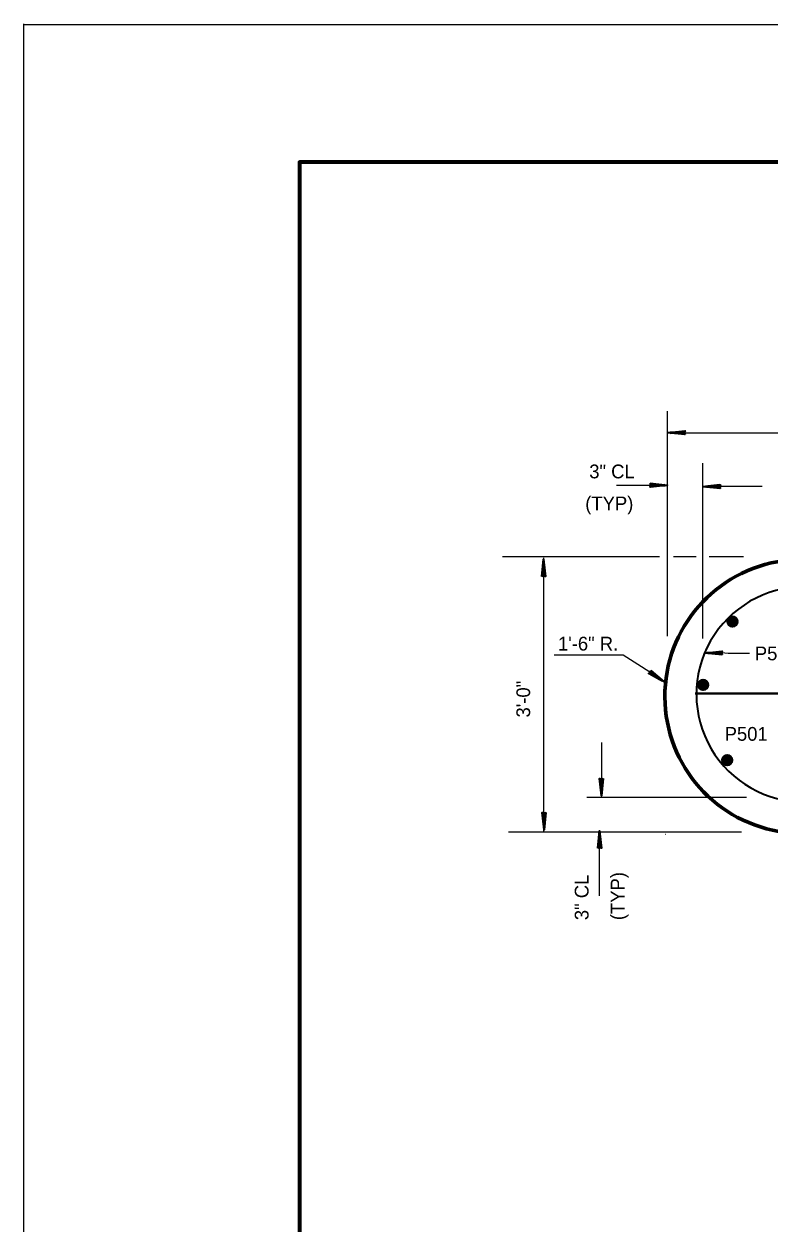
# Model space of a CAD drawing. Extents: x 3.64 to 6.84, y -0.8 to 1.19.
# Drawn here: x 3.645 to 4.095, y 0.467 to 1.192 of the extents above; entities that cross this region are included whole.
import ezdxf

# ---------------------------------------------------------------- set-up
doc = ezdxf.new("R2010")
doc.units = 0
doc.header["$LTSCALE"] = 0.0033
doc.layers.add('1', color=7, linetype='Continuous', lineweight=40)

msp = doc.modelspace()

# ---------------------------------------------------------------- linework, layer by layer
at = {"layer": '1', "lineweight": 13}
for p, q in [((3.644833, -0.795833), (3.644833, 1.192417)), ((3.644833, 1.192083), (6.84125, 1.192083)), ((4.034167, 0.822083), (4.034167, 0.958167)), ((4.034083, 0.945083), (4.494, 0.945083)), ((4.0555, 0.82075), (4.0555, 0.926667)), ((4.003333, 0.9135), (4.024167, 0.9135)), ((4.056167, 0.912833), (4.09125, 0.912833)), ((3.934333, 0.87025), (4.029167, 0.87025)), ((3.959167, 0.8695), (3.959167, 0.7035)), ((4.034167, 0.86875), (4.034167, 0.868833)), ((4.037667, 0.87025), (4.051333, 0.87025)), ((4.059333, 0.87025), (4.080083, 0.87025)), ((3.99425, 0.75775), (3.99425, 0.726333)), ((3.98525, 0.724667), (4.081917, 0.724667)), ((3.937917, 0.70375), (4.07875, 0.70375)), ((3.993, 0.665083), (3.993, 0.702583)), ((4.033167, 0.702083), (4.032833, 0.702083))]:
    msp.add_line(p, q, dxfattribs=at)
at = {"layer": '1', "lineweight": 35}
for p, q in [((4.04475, 0.945083), (4.034167, 0.945083)), ((4.0445, 0.94425), (4.036667, 0.94525)), ((4.0445, 0.94425), (4.036667, 0.945083)), ((4.0445, 0.944083), (4.036667, 0.945)), ((4.0445, 0.944083), (4.036667, 0.945)), ((4.0445, 0.944167), (4.036667, 0.945)), ((4.0445, 0.946167), (4.037167, 0.945333)), ((4.0445, 0.946), (4.037167, 0.94525)), ((4.0445, 0.945917), (4.037167, 0.945083)), ((4.044583, 0.94575), (4.03725, 0.945)), ((4.02375, 0.9145), (4.031583, 0.913583)), ((4.02375, 0.9145), (4.031583, 0.913583)), ((4.02375, 0.914417), (4.031583, 0.913583)), ((4.02375, 0.914333), (4.031583, 0.9135)), ((4.02375, 0.914333), (4.031583, 0.913333)), ((4.0235, 0.9135), (4.034083, 0.9135)), ((4.023667, 0.912833), (4.031, 0.913583)), ((4.02375, 0.912667), (4.031083, 0.9135)), ((4.02375, 0.912583), (4.031083, 0.913333)), ((4.02375, 0.912417), (4.031083, 0.91325)), ((4.066083, 0.9125), (4.0555, 0.9125)), ((4.065833, 0.911667), (4.058, 0.912667)), ((4.065833, 0.911667), (4.058, 0.9125)), ((4.065833, 0.9115), (4.058, 0.912417)), ((4.065833, 0.9115), (4.058, 0.912417)), ((4.065833, 0.911583), (4.058, 0.912417)), ((4.065833, 0.913583), (4.0585, 0.91275)), ((4.065833, 0.913417), (4.0585, 0.912667)), ((4.065833, 0.913333), (4.0585, 0.9125)), ((4.065917, 0.913167), (4.058583, 0.912417)), ((3.958167, 0.858417), (3.959083, 0.86625)), ((3.958167, 0.858417), (3.959083, 0.86625)), ((3.95825, 0.858417), (3.959083, 0.86625)), ((3.958333, 0.858417), (3.959167, 0.86625)), ((3.958333, 0.858417), (3.959333, 0.86625)), ((3.959833, 0.858333), (3.959083, 0.865667)), ((3.959167, 0.858167), (3.959167, 0.86875)), ((3.96, 0.858417), (3.959167, 0.86575)), ((3.960083, 0.858417), (3.959333, 0.86575)), ((3.96025, 0.858417), (3.959417, 0.86575)), ((4.067, 0.812917), (4.059667, 0.812083)), ((4.067, 0.81275), (4.059667, 0.812)), ((4.067, 0.812667), (4.059667, 0.811833)), ((4.067083, 0.8125), (4.05975, 0.81175)), ((4.06725, 0.811833), (4.056667, 0.811833)), ((4.067, 0.811), (4.059167, 0.812)), ((4.067, 0.811), (4.059167, 0.811833)), ((4.067, 0.810833), (4.059167, 0.81175)), ((4.067, 0.810833), (4.059167, 0.81175)), ((4.067, 0.810917), (4.059167, 0.81175)), ((4.022917, 0.7995), (4.029417, 0.796)), ((4.023, 0.799667), (4.029583, 0.796167)), ((4.023083, 0.799917), (4.029583, 0.79625)), ((4.023083, 0.799583), (4.0295, 0.796)), ((4.023333, 0.800583), (4.032, 0.7945)), ((4.024, 0.801083), (4.03, 0.795917)), ((4.024, 0.801083), (4.029833, 0.79575)), ((4.024083, 0.801167), (4.030083, 0.796)), ((4.024167, 0.801167), (4.030083, 0.796)), ((4.024167, 0.801167), (4.030083, 0.796)), ((3.993083, 0.735833), (3.993917, 0.7285)), ((3.99325, 0.735833), (3.994, 0.7285)), ((3.993333, 0.735833), (3.994167, 0.7285)), ((3.9935, 0.735917), (3.99425, 0.728583)), ((3.995, 0.735833), (3.994, 0.728)), ((3.994167, 0.736083), (3.994167, 0.7255)), ((3.995, 0.735833), (3.994167, 0.728)), ((3.995167, 0.735833), (3.99425, 0.728)), ((3.995167, 0.735833), (3.99425, 0.728)), ((3.995083, 0.735833), (3.99425, 0.728)), ((3.958333, 0.71525), (3.959167, 0.707917)), ((3.9585, 0.71525), (3.95925, 0.707917)), ((3.958583, 0.71525), (3.959417, 0.707917)), ((3.95875, 0.715333), (3.9595, 0.708)), ((3.96025, 0.71525), (3.95925, 0.707417)), ((3.959417, 0.7155), (3.959417, 0.704917)), ((3.96025, 0.71525), (3.959417, 0.707417)), ((3.960417, 0.71525), (3.9595, 0.707417)), ((3.960417, 0.71525), (3.9595, 0.707417)), ((3.960333, 0.71525), (3.9595, 0.707417)), ((3.993, 0.693833), (3.993, 0.704417)), ((3.992, 0.694083), (3.992917, 0.701917)), ((3.992, 0.694083), (3.992917, 0.701917)), ((3.992083, 0.694083), (3.992917, 0.701917)), ((3.992167, 0.694083), (3.993, 0.701917)), ((3.992167, 0.694083), (3.993167, 0.701917)), ((3.993667, 0.694), (3.992917, 0.701333)), ((3.993833, 0.694083), (3.993, 0.701417)), ((3.993917, 0.694083), (3.993167, 0.701417)), ((3.994083, 0.694083), (3.99325, 0.701417))]:
    msp.add_line(p, q, dxfattribs=at)
at = {"layer": '1', "lineweight": 60}
for p, q in [((4.075917, 0.830333), (4.071167, 0.829583)), ((4.071583, 0.8325), (4.071417, 0.829583)), ((4.071833, 0.8325), (4.071583, 0.829583)), ((4.072, 0.8325), (4.071833, 0.8295)), ((4.072167, 0.8325), (4.071917, 0.8295)), ((4.072333, 0.8325), (4.072167, 0.8295)), ((4.072583, 0.8325), (4.072417, 0.8295)), ((4.072833, 0.8325), (4.072583, 0.8295)), ((4.072917, 0.832417), (4.07275, 0.8295)), ((4.073083, 0.832417), (4.072917, 0.8295)), ((4.07325, 0.832417), (4.073083, 0.8295)), ((4.0735, 0.832417), (4.07325, 0.8295)), ((4.073667, 0.832417), (4.0735, 0.8295)), ((4.073917, 0.832333), (4.073667, 0.829417)), ((4.074167, 0.832333), (4.073917, 0.829417)), ((4.074333, 0.832333), (4.074167, 0.829417)), ((4.074417, 0.832333), (4.07425, 0.829417)), ((4.074583, 0.832333), (4.074417, 0.829417)), ((4.074667, 0.832333), (4.0745, 0.829417)), ((4.074917, 0.83225), (4.074667, 0.829333)), ((4.075083, 0.83225), (4.074917, 0.829333)), ((4.07525, 0.83225), (4.075, 0.829333)), ((4.075417, 0.83225), (4.07525, 0.829333)), ((4.075667, 0.83225), (4.0755, 0.829333)), ((4.075917, 0.830333), (4.07575, 0.832167)), ((4.058167, 0.792), (4.053417, 0.79125)), ((4.053833, 0.794167), (4.053667, 0.79125)), ((4.054083, 0.794167), (4.053833, 0.79125)), ((4.05425, 0.794167), (4.054083, 0.791167)), ((4.054417, 0.794167), (4.054167, 0.791167)), ((4.054583, 0.794167), (4.054417, 0.791167)), ((4.054833, 0.794167), (4.054667, 0.791167)), ((4.055083, 0.794167), (4.054833, 0.791167)), ((4.055167, 0.794083), (4.055, 0.791167)), ((4.055333, 0.794083), (4.055167, 0.791167)), ((4.0555, 0.794083), (4.055333, 0.791167)), ((4.05575, 0.794083), (4.0555, 0.791167)), ((4.055917, 0.794083), (4.05575, 0.791167)), ((4.056167, 0.794), (4.055917, 0.791083)), ((4.056417, 0.794), (4.056167, 0.791083)), ((4.056583, 0.794), (4.056417, 0.791083)), ((4.056667, 0.794), (4.0565, 0.791083)), ((4.056833, 0.794), (4.056667, 0.791083)), ((4.056917, 0.794), (4.05675, 0.791083)), ((4.057167, 0.793917), (4.056917, 0.791)), ((4.057333, 0.793917), (4.057167, 0.791)), ((4.0575, 0.793917), (4.05725, 0.791)), ((4.057667, 0.793917), (4.0575, 0.791)), ((4.057917, 0.793917), (4.05775, 0.791)), ((4.058167, 0.792), (4.058, 0.793833)), ((4.068417, 0.748667), (4.06825, 0.74575)), ((4.068667, 0.748667), (4.068417, 0.74575)), ((4.068833, 0.748667), (4.068667, 0.745667)), ((4.069, 0.748667), (4.06875, 0.745667)), ((4.069167, 0.748667), (4.069, 0.745667)), ((4.069417, 0.748667), (4.06925, 0.745667)), ((4.069667, 0.748667), (4.069417, 0.745667)), ((4.06975, 0.748583), (4.069583, 0.745667)), ((4.069917, 0.748583), (4.06975, 0.745667)), ((4.070083, 0.748583), (4.069917, 0.745667)), ((4.070333, 0.748583), (4.070083, 0.745667)), ((4.0705, 0.748583), (4.070333, 0.745667)), ((4.07075, 0.7485), (4.0705, 0.745583)), ((4.071, 0.7485), (4.07075, 0.745583)), ((4.071167, 0.7485), (4.071, 0.745583)), ((4.07125, 0.7485), (4.071083, 0.745583)), ((4.071417, 0.7485), (4.07125, 0.745583)), ((4.0715, 0.7485), (4.071333, 0.745583)), ((4.07175, 0.748417), (4.0715, 0.7455)), ((4.071917, 0.748417), (4.07175, 0.7455)), ((4.072083, 0.748417), (4.071833, 0.7455)), ((4.07225, 0.748417), (4.072083, 0.7455)), ((4.0725, 0.748417), (4.072333, 0.7455)), ((4.07275, 0.7465), (4.072583, 0.748333)), ((4.07275, 0.7465), (4.068, 0.74575))]:
    msp.add_line(p, q, dxfattribs=at)
at = {"layer": '1'}
for p, q in [((4.071167, 0.82975), (4.075, 0.829)), ((4.071167, 0.829583), (4.075, 0.828833)), ((4.07125, 0.83025), (4.075167, 0.8295)), ((4.07125, 0.830083), (4.075083, 0.829333)), ((4.07125, 0.829833), (4.075083, 0.829167)), ((4.071333, 0.8325), (4.075917, 0.830333)), ((4.071333, 0.830667), (4.07525, 0.829917)), ((4.071417, 0.831083), (4.07525, 0.830333)), ((4.071417, 0.830917), (4.07525, 0.830167)), ((4.0715, 0.8315), (4.075333, 0.830833)), ((4.0715, 0.831333), (4.075333, 0.830583)), ((4.071583, 0.832083), (4.0755, 0.831333)), ((4.071583, 0.831917), (4.0755, 0.831167)), ((4.071583, 0.831667), (4.075417, 0.830917)), ((4.071667, 0.8325), (4.075583, 0.831833)), ((4.071667, 0.832333), (4.075583, 0.831583)), ((4.07175, 0.832833), (4.075583, 0.832167)), ((4.0755, 0.829333), (4.07175, 0.828917)), ((4.073667, 0.832), (4.075, 0.833)), ((4.07575, 0.832167), (4.0745, 0.833333)), ((4.053417, 0.791417), (4.05725, 0.790667)), ((4.053417, 0.79125), (4.05725, 0.7905)), ((4.0535, 0.791917), (4.057417, 0.791167)), ((4.0535, 0.79175), (4.057333, 0.791)), ((4.0535, 0.7915), (4.057333, 0.790833)), ((4.053583, 0.794167), (4.058167, 0.792)), ((4.053583, 0.792333), (4.0575, 0.791583)), ((4.053667, 0.79275), (4.0575, 0.792)), ((4.053667, 0.792583), (4.0575, 0.791833)), ((4.05375, 0.793167), (4.057583, 0.7925)), ((4.05375, 0.793), (4.057583, 0.79225)), ((4.053833, 0.79375), (4.05775, 0.793)), ((4.053833, 0.793583), (4.05775, 0.792833)), ((4.053833, 0.793333), (4.057667, 0.792583)), ((4.053917, 0.794167), (4.057833, 0.7935)), ((4.053917, 0.794), (4.057833, 0.79325)), ((4.054, 0.7945), (4.057833, 0.793833)), ((4.05775, 0.791), (4.054, 0.790583)), ((4.055917, 0.793667), (4.05725, 0.794667)), ((4.058, 0.793833), (4.05675, 0.795)), ((4.050917, 0.7875), (4.474833, 0.7875)), ((4.068167, 0.748667), (4.07275, 0.7465)), ((4.06825, 0.74725), (4.072083, 0.7465)), ((4.06825, 0.747083), (4.072083, 0.746333)), ((4.068333, 0.747667), (4.072167, 0.747)), ((4.068333, 0.7475), (4.072167, 0.74675)), ((4.068417, 0.74825), (4.072333, 0.7475)), ((4.068417, 0.748083), (4.072333, 0.747333)), ((4.068417, 0.747833), (4.07225, 0.747083)), ((4.0685, 0.748667), (4.072417, 0.748)), ((4.0685, 0.7485), (4.072417, 0.74775)), ((4.068583, 0.749), (4.072417, 0.748333)), ((4.0705, 0.748167), (4.071833, 0.749167)), ((4.072583, 0.748333), (4.071333, 0.7495)), ((4.068, 0.745917), (4.071833, 0.745167)), ((4.068, 0.74575), (4.071833, 0.745)), ((4.068083, 0.746417), (4.072, 0.745667)), ((4.068083, 0.74625), (4.071917, 0.7455)), ((4.068083, 0.746), (4.071917, 0.745333)), ((4.068167, 0.746833), (4.072083, 0.746083)), ((4.072333, 0.7455), (4.068583, 0.745083))]:
    msp.add_line(p, q, dxfattribs=at)
at = {"layer": '1', "lineweight": 70}
msp.add_lwpolyline([(6.75825, -0.711333), (6.75825, 1.10875), (3.811583, 1.10875), (3.811583, -0.711333)], dxfattribs=at)
at = {"layer": '1', "lineweight": 35}
for points in [[(4.04475, 0.944), (4.034167, 0.945083), (4.04475, 0.94625), (4.044167, 0.945083)], [(4.044, 0.945), (4.039333, 0.944917), (4.039333, 0.945), (4.04025, 0.945), (4.044, 0.944917), (4.041, 0.944833), (4.044167, 0.94475), (4.041917, 0.944667), (4.044167, 0.944583), (4.040667, 0.944833), (4.036, 0.945), (4.036917, 0.94525), (4.035667, 0.94525), (4.044, 0.94525), (4.041583, 0.945417), (4.044167, 0.945417), (4.038833, 0.945), (4.044167, 0.945667)], [(4.0235, 0.914583), (4.034083, 0.9135), (4.0235, 0.912333), (4.024083, 0.9135)], [(4.02425, 0.913583), (4.028917, 0.913667), (4.028917, 0.913583), (4.028, 0.913583), (4.02425, 0.913667), (4.02725, 0.91375), (4.024083, 0.913833), (4.026333, 0.913917), (4.024083, 0.914), (4.027583, 0.91375), (4.03225, 0.913583), (4.031333, 0.913333), (4.032583, 0.913333), (4.02425, 0.913333), (4.026667, 0.913167), (4.024083, 0.913167), (4.029417, 0.913583), (4.024083, 0.912917)], [(4.066083, 0.911417), (4.0555, 0.9125), (4.066083, 0.913667), (4.0655, 0.9125)], [(4.065333, 0.912417), (4.060667, 0.912333), (4.060667, 0.912417), (4.061583, 0.912417), (4.065333, 0.912333), (4.062333, 0.91225), (4.0655, 0.912167), (4.06325, 0.912083), (4.0655, 0.912), (4.062, 0.91225), (4.057333, 0.912417), (4.05825, 0.912667), (4.057, 0.912667), (4.065333, 0.912667), (4.062917, 0.912833), (4.0655, 0.912833), (4.060167, 0.912417), (4.0655, 0.913083)], [(3.958083, 0.858167), (3.959167, 0.86875), (3.960333, 0.858167), (3.959167, 0.85875)], [(3.959083, 0.858917), (3.959, 0.863583), (3.959083, 0.863583), (3.959083, 0.862667), (3.959, 0.858917), (3.958917, 0.861917), (3.958833, 0.85875), (3.95875, 0.861), (3.958667, 0.85875), (3.958917, 0.86225), (3.959083, 0.866917), (3.959333, 0.866), (3.959333, 0.86725), (3.959333, 0.858917), (3.9595, 0.861333), (3.9595, 0.85875), (3.959083, 0.864083), (3.95975, 0.85875)], [(4.06725, 0.81075), (4.056667, 0.811833), (4.06725, 0.813), (4.066667, 0.811833)], [(4.0665, 0.81175), (4.061833, 0.811667), (4.061833, 0.81175), (4.06275, 0.81175), (4.0665, 0.811667), (4.0635, 0.811583), (4.066667, 0.8115), (4.064417, 0.811417), (4.066667, 0.811333), (4.063167, 0.811583), (4.0585, 0.81175), (4.059417, 0.812), (4.058167, 0.812), (4.0665, 0.812), (4.064083, 0.812167), (4.066667, 0.812167), (4.061333, 0.81175), (4.066667, 0.812417)], [(4.024, 0.801333), (4.032, 0.7945), (4.022667, 0.799583), (4.023833, 0.800167)], [(4.024, 0.800083), (4.027917, 0.7975), (4.027833, 0.7975), (4.027083, 0.798), (4.024083, 0.80025), (4.026583, 0.798583), (4.024083, 0.8005), (4.025917, 0.799167), (4.024167, 0.800583), (4.026833, 0.798333), (4.030583, 0.7955), (4.029667, 0.795833), (4.03075, 0.795083), (4.023833, 0.799917), (4.02575, 0.798417), (4.023583, 0.799917), (4.02825, 0.797167), (4.023417, 0.79975)], [(3.99525, 0.736083), (3.994167, 0.7255), (3.993, 0.736083), (3.994167, 0.7355)], [(3.99425, 0.735333), (3.994333, 0.730667), (3.99425, 0.730667), (3.99425, 0.731583), (3.994333, 0.735333), (3.994417, 0.732333), (3.9945, 0.7355), (3.994583, 0.73325), (3.994667, 0.7355), (3.994417, 0.732), (3.99425, 0.727333), (3.994, 0.72825), (3.994, 0.727), (3.994, 0.735333), (3.993833, 0.732917), (3.993833, 0.7355), (3.99425, 0.730167), (3.993583, 0.7355)], [(3.9605, 0.7155), (3.959417, 0.704917), (3.95825, 0.7155), (3.959417, 0.714917)], [(3.9595, 0.71475), (3.959583, 0.710083), (3.9595, 0.710083), (3.9595, 0.711), (3.959583, 0.71475), (3.959667, 0.71175), (3.95975, 0.714917), (3.959833, 0.712667), (3.959917, 0.714917), (3.959667, 0.711417), (3.9595, 0.70675), (3.95925, 0.707667), (3.95925, 0.706417), (3.95925, 0.71475), (3.959083, 0.712333), (3.959083, 0.714917), (3.9595, 0.709583), (3.958833, 0.714917)], [(3.991917, 0.693833), (3.993, 0.704417), (3.994167, 0.693833), (3.993, 0.694417)], [(3.992917, 0.694583), (3.992833, 0.69925), (3.992917, 0.69925), (3.992917, 0.698333), (3.992833, 0.694583), (3.99275, 0.697583), (3.992667, 0.694417), (3.992583, 0.696667), (3.9925, 0.694417), (3.99275, 0.697917), (3.992917, 0.702583), (3.993167, 0.701667), (3.993167, 0.702917), (3.993167, 0.694583), (3.993333, 0.697), (3.993333, 0.694417), (3.992917, 0.69975), (3.993583, 0.694417)]]:
    msp.add_lwpolyline(points, close=True, dxfattribs=at)
for points in [[(4.044, 0.945), (4.044417, 0.94425), (4.044167, 0.9445), (4.044, 0.944833), (4.04375, 0.94475), (4.043917, 0.944417), (4.044083, 0.945167), (4.04425, 0.945667), (4.0445, 0.946083)], [(4.02425, 0.913583), (4.023833, 0.914333), (4.024083, 0.914083), (4.02425, 0.91375), (4.0245, 0.913833), (4.024333, 0.914167), (4.024167, 0.913417), (4.024, 0.912917), (4.02375, 0.9125)], [(4.065333, 0.912417), (4.06575, 0.911667), (4.0655, 0.911917), (4.065333, 0.91225), (4.065083, 0.912167), (4.06525, 0.911833), (4.065417, 0.912583), (4.065583, 0.913083), (4.065833, 0.9135)], [(3.959083, 0.858917), (3.958333, 0.8585), (3.958583, 0.85875), (3.958917, 0.858917), (3.958833, 0.859167), (3.9585, 0.859), (3.95925, 0.858833), (3.95975, 0.858667), (3.960167, 0.858417)], [(4.0665, 0.81175), (4.066917, 0.811), (4.066667, 0.81125), (4.0665, 0.811583), (4.06625, 0.8115), (4.066417, 0.811167), (4.066583, 0.811917), (4.06675, 0.812417), (4.067, 0.812833)], [(4.024, 0.800083), (4.024083, 0.801), (4.024167, 0.800667), (4.024167, 0.800333), (4.024417, 0.80025), (4.024417, 0.800667), (4.023833, 0.800083), (4.023417, 0.799833), (4.023, 0.7995)], [(3.99425, 0.735333), (3.995, 0.73575), (3.99475, 0.7355), (3.994417, 0.735333), (3.9945, 0.735083), (3.994833, 0.73525), (3.994083, 0.735417), (3.993583, 0.735583), (3.993167, 0.735833)], [(3.9595, 0.71475), (3.96025, 0.715167), (3.96, 0.714917), (3.959667, 0.71475), (3.95975, 0.7145), (3.960083, 0.714667), (3.959333, 0.714833), (3.958833, 0.715), (3.958417, 0.71525)], [(3.992917, 0.694583), (3.992167, 0.694167), (3.992417, 0.694417), (3.99275, 0.694583), (3.992667, 0.694833), (3.992333, 0.694667), (3.993083, 0.6945), (3.993583, 0.694333), (3.994, 0.694083)]]:
    msp.add_lwpolyline(points, dxfattribs=at)
at = {"layer": '1', "lineweight": 60}
for points in [[(4.07075, 0.830833), (4.075917, 0.8315), (4.071333, 0.8325)], [(4.075, 0.828833), (4.075, 0.833), (4.073333, 0.828333), (4.073833, 0.8335), (4.07175, 0.828917), (4.0725, 0.833417), (4.074083, 0.828417), (4.070917, 0.83175), (4.07575, 0.832167), (4.0725, 0.8285), (4.0745, 0.833333), (4.071333, 0.8325), (4.071167, 0.829583)], [(4.07175, 0.828917), (4.07325, 0.831167), (4.071083, 0.832083), (4.073083, 0.8335), (4.07325, 0.83125), (4.074917, 0.828917), (4.070917, 0.83125), (4.073667, 0.832)], [(4.0745, 0.833333), (4.07325, 0.831167), (4.0755, 0.829333)], [(4.053, 0.7925), (4.058167, 0.793167), (4.053583, 0.794167)], [(4.05725, 0.7905), (4.05725, 0.794667), (4.055583, 0.79), (4.056083, 0.795167), (4.054, 0.790583), (4.05475, 0.795083), (4.056333, 0.790083), (4.053167, 0.793417), (4.058, 0.793833), (4.05475, 0.790167), (4.05675, 0.795), (4.053583, 0.794167), (4.053417, 0.79125)], [(4.054, 0.790583), (4.0555, 0.792833), (4.053333, 0.79375), (4.055333, 0.795167), (4.0555, 0.792917), (4.057167, 0.790583), (4.053167, 0.792917), (4.055917, 0.793667)], [(4.05675, 0.795), (4.0555, 0.792833), (4.05775, 0.791)], [(4.067583, 0.747), (4.07275, 0.747667), (4.068167, 0.748667)], [(4.071833, 0.745), (4.071833, 0.749167), (4.070167, 0.7445), (4.070667, 0.749667), (4.068583, 0.745083), (4.069333, 0.749583), (4.070917, 0.744583), (4.06775, 0.747917), (4.072583, 0.748333), (4.069333, 0.744667), (4.071333, 0.7495), (4.068167, 0.748667), (4.068, 0.74575)], [(4.068583, 0.745083), (4.070083, 0.747333), (4.067917, 0.74825), (4.069917, 0.749667), (4.070083, 0.747417), (4.07175, 0.745083), (4.06775, 0.747417), (4.0705, 0.748167)], [(4.071333, 0.7495), (4.070083, 0.747333), (4.072333, 0.7455)]]:
    msp.add_lwpolyline(points, dxfattribs=at)
at = {"layer": '1'}
for points in [[(4.071167, 0.829583), (4.07325, 0.828333), (4.075, 0.828833), (4.075917, 0.830333)], [(4.053417, 0.79125), (4.0555, 0.79), (4.05725, 0.7905), (4.058167, 0.792)], [(4.254417, 0.7875), (4.175833, 0.7875), (4.0545, 0.7875)], [(4.068, 0.74575), (4.070083, 0.7445), (4.071833, 0.745), (4.07275, 0.7465)]]:
    msp.add_lwpolyline(points, dxfattribs=at)
at = {"layer": '1', "lineweight": 13}
msp.add_lwpolyline([(3.965583, 0.810917), (4.00725, 0.810917), (4.03225, 0.794917)], dxfattribs=at)
at = {"layer": '1', "lineweight": 60}
for centre in [(4.073417, 0.830933), (4.055667, 0.7926), (4.07025, 0.7471)]:
    msp.add_circle(centre, 0.00264, dxfattribs=at)
msp.add_arc((4.115333, 0.785667), 0.082833, 97.64809, 263.01663, dxfattribs=at)
at = {"layer": '1', "lineweight": 35}
msp.add_arc((4.116583, 0.786917), 0.065042, 90, 270.57654, dxfattribs=at)
at = {"layer": '1', "lineweight": 13}
msp.add_arc((4.076997, 0.939971), 0.128228, 265.34169, 272.98148, dxfattribs=at)

# ---------------------------------------------------------------- texts
at = {"layer": '1'}
for s, p in [('3" CL', (3.98675, 0.917583)), ('(TYP)', (3.984333, 0.89825)), ('1\'-6" R.', (3.967833, 0.813417)), ('P510', (4.086917, 0.8075)), ('P501', (4.068667, 0.758833))]:
    msp.add_text(s, height=0.008334, dxfattribs=at).set_placement(p)
for s, height, p in [('3\'-0"', 0.008333, (3.951, 0.772917)), ('3" CL', 0.008334, (3.986333, 0.650333)), ('(TYP)', 0.008334, (4.008083, 0.650333))]:
    msp.add_text(s, height=height, rotation=90, dxfattribs=at).set_placement(p)

doc.saveas('drawing.dxf')
